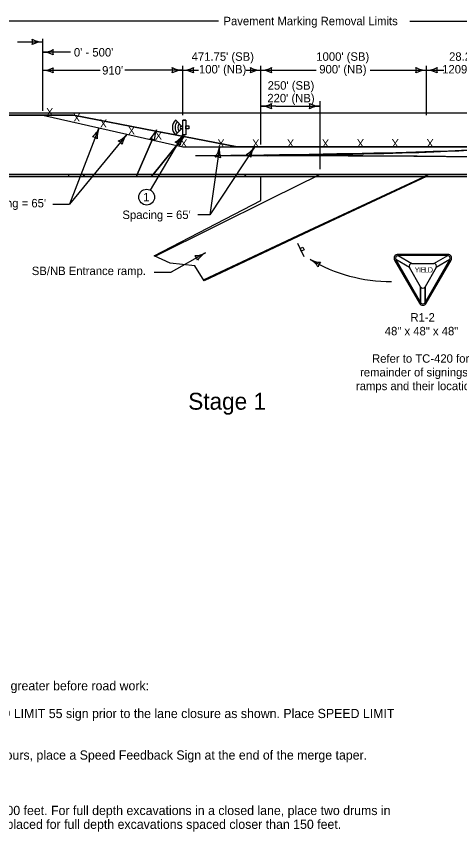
# Model space of a CAD drawing. Extents: x 10124 to 16850, y 7924 to 12166.
# Drawn here: x 11298 to 12139, y 8001 to 9547 of the extents above; entities that cross this region are included whole.
import ezdxf

# ---------------------------------------------------------------- set-up
doc = ezdxf.new("R2010")
doc.units = 0
for name, color, linetype in [('dsnShtPlotShapeBatchPrint', 7, 'Continuous'), ('dsnStdBlock', 7, 'Continuous'), ('dsnStdLabel', 7, 'Continuous'), ('dsnStdLineWork', 7, 'Continuous'), ('dsnStdShading', 7, 'Continuous'), ('Level 2', 7, 'Continuous'), ('SheetText', 7, 'Continuous')]:
    doc.layers.add(name, color=color, linetype=linetype)

msp = doc.modelspace()

# ---------------------------------------------------------------- linework, layer by layer
at = {"layer": 'dsnShtPlotShapeBatchPrint'}
msp.add_circle((11545.2, 9204), 15, dxfattribs=at)
at = {"layer": 'dsnStdLabel'}
for p, q in [((11619.5, 9349.7), (11619.5, 9322.2)), ((11831.5, 9116.4), (11843.2, 9091.5)), ((12116.2, 9095.5), (12022.1, 9095.5)), ((12015.6, 9084.3), (12062.7, 9002.8)), ((12075.6, 9002.8), (12122.7, 9084.3)), ((12064.8, 9034.1), (12064.8, 9004.1)), ((12073.5, 9004.1), (12073.5, 9034.1))]:
    msp.add_line(p, q, dxfattribs=at)
for points in [[(11613.9, 9322.2), (11613.9, 9349.7), (11619.5, 9349.7), (11619.5, 9322.2)], [(11619.5, 9333.3), (11619.5, 9338.9), (11625.2, 9338.9), (11625.2, 9333.3)], [(11838.6, 9101.5), (11836.2, 9106.6), (11841.3, 9109), (11843.7, 9103.9)], [(12116.2, 9093), (12022.1, 9093), (12048.1, 9078), (12090.2, 9078), (12116.2, 9093)], [(12017.8, 9085.5), (12064.8, 9004.1), (12064.8, 9034.1), (12043.8, 9070.5), (12017.8, 9085.5)], [(12073.5, 9004.1), (12120.5, 9085.5), (12094.5, 9070.5), (12073.5, 9034.1), (12073.5, 9004.1)]]:
    msp.add_lwpolyline(points, close=True, dxfattribs=at)
for centre, radius, start, end in [((12022.1, 9088), 7.5, 90.0002, 209.9999), ((12022.1, 9088), 5, 89.9999, 210.0002), ((12022.1, 9088), 5, 89.9999, 210.0002), ((12116.2, 9088), 7.5, 330.0002, 89.9999), ((12116.2, 9088), 5, 330.0002, 89.9999), ((12116.2, 9088), 5, 330.0002, 89.9999), ((12048.1, 9073), 5, 90.0002, 209.9999), ((12048.1, 9073), 5, 90.0002, 209.9999), ((12090.2, 9073), 5, 330.0002, 89.9999), ((12090.2, 9073), 5, 330.0002, 89.9999), ((12069.1, 9036.6), 5, 209.9999, 330.0002), ((12069.1, 9006.6), 7.5, 209.9999, 330.0002), ((12069.1, 9006.6), 5, 210.0002, 330.0016)]:
    msp.add_arc(centre, radius, start, end, dxfattribs=at)
at = {"layer": 'dsnStdLineWork'}
for p, q in [((10151.9, 9359), (11348.1, 9359)), ((11348.1, 9359), (11613.9, 9299.3)), ((11613.9, 9299.3), (12271.7, 9299.3)), ((10144, 9247), (11762.1, 9247)), ((11762.1, 9247), (11874.2, 9247)), ((12080.5, 9247), (12270.6, 9247))]:
    msp.add_line(p, q, dxfattribs=at)
for points in [[(11874.2, 9247), (11780.9, 9200.8), (11562, 9092.3)], [(11653.1, 9047.2), (11853.4, 9141.4), (12080.5, 9247)]]:
    msp.add_lwpolyline(points, dxfattribs=at)
at = {"layer": 'dsnStdShading'}
for p, q in [((12409.6, 9363), (11195.2, 9363)), ((11406.5, 9359), (11195.2, 9359)), ((11195.2, 9359), (11406.5, 9359)), ((11562.7, 9329), (11406.5, 9359)), ((11406.5, 9359), (11562.7, 9329)), ((11562.8, 9329), (11615.6, 9318.8)), ((11615.6, 9318.8), (11562.8, 9329)), ((11615.7, 9318.8), (11717.2, 9299.3)), ((11717.2, 9299.3), (11615.7, 9318.8)), ((11527.5, 9247), (11556.1, 9313.6)), ((11556.1, 9313.6), (11527.5, 9247)), ((11557.5, 9247), (11604.7, 9305.4)), ((11604.7, 9305.4), (11557.5, 9247)), ((11717.2, 9299.3), (12245.9, 9299.3)), ((12278.7, 9299.3), (11717.2, 9299.3)), ((11527.5, 9247), (10143.9, 9247)), ((10147.9, 9243), (11554.2, 9243)), ((10147.9, 9243), (11525.7, 9243)), ((10978.7, 9247), (11527.5, 9247)), ((11398.2, 9247), (11396.6, 9243)), ((11396.6, 9243), (11425.2, 9243)), ((11428.3, 9247), (11398.2, 9247)), ((11425.2, 9243), (11428.3, 9247)), ((11525.7, 9243), (11527.5, 9247)), ((11527.5, 9247), (11525.7, 9243)), ((11525.7, 9243), (11554.2, 9243)), ((11557.5, 9247), (11527.5, 9247)), ((11527.5, 9247), (11557.5, 9247)), ((11557.5, 9247), (11554.2, 9243)), ((11554.2, 9243), (11557.5, 9247)), ((11554.2, 9243), (12204, 9243)), ((12207, 9247), (11557.5, 9247)), ((11733.4, 9247), (11730.5, 9243)), ((11730.5, 9243), (12280.5, 9243)), ((12285.5, 9247), (11733.4, 9247)), ((11762.1, 9197.5), (11762.1, 9243)), ((11762.1, 9243), (12076.1, 9243)), ((12076.1, 9243), (11854.4, 9139.2)), ((11559.7, 9092.5), (11762.1, 9197.5)), ((11854.4, 9139.2), (11654.4, 9045.2)), ((11589.8, 9078.9), (11559.7, 9092.5)), ((11636.6, 9073.9), (11589.8, 9078.9)), ((11654.4, 9045.2), (11636.6, 9073.9))]:
    msp.add_line(p, q, dxfattribs=at)
for points in [[(11563.3, 9330.3), (11563.7, 9331.2), (11563.7, 9331.2)], [(11563.3, 9330.3), (11563.3, 9330.3)], [(11615.7, 9318.8), (11615.6, 9318.8)], [(11616.4, 9319.8), (11616.8, 9320.3), (11616.8, 9320.3)], [(11557.5, 9247), (12276.5, 9247), (12274.6, 9247)]]:
    msp.add_lwpolyline(points, dxfattribs=at)
for centre, radius, start, end in [((11524.5, 9347.6), 42.5, 309.2655, 336.072), ((11524.5, 9347.6), 42.5, 309.2655, 334.0959), ((11602.9, 9314.8), 42.5, 160.5422, 185.4105), ((11602.9, 9314.8), 42.5, 160.5422, 185.4105), ((11524.5, 9347.6), 42.5, 334.0959, 336.072), ((11602.9, 9314.8), 42.5, 157.3556, 160.5422), ((11602.9, 9314.8), 42.5, 158.6034, 160.5422), ((11524.5, 9347.6), 42.5, 337.3204, 337.338), ((11583.6, 9346.8), 42.5, 293.3393, 318.8219), ((11583.6, 9346.8), 42.5, 293.3393, 318.8219), ((11650.1, 9293.8), 42.5, 143.9415, 169.4842), ((11650.1, 9293.8), 42.5, 143.9415, 169.4842), ((11583.6, 9346.8), 42.5, 318.8219, 320.5615), ((11650.1, 9293.8), 42.5, 141.4294, 143.9415), ((11583.6, 9346.8), 42.5, 321.3942, 321.4118), ((11550, 9298.3), 16.4, 68.0792, 85.0713), ((11550, 9298.3), 16.4, 49.6046, 85.0713), ((11550, 9298.3), 16.4, 49.6046, 68.0792), ((11594.6, 9292.5), 16.4, 51.9095, 69.1451), ((11594.6, 9292.5), 16.4, 33.6784, 69.1451), ((11594.6, 9292.5), 16.4, 33.6784, 51.9095)]:
    msp.add_arc(centre, radius, start, end, dxfattribs=at)
for centre, major_axis, ratio, start_param, end_param in [((6674, 9331.8), (5526.2, -32.7), 0.008175, 5.82835, 6.279465), ((8643.8, 9315.3), (3556.3, -16.3), 0.011041, 5.788962, 6.278612), ((9224.4, 9266.8), (2972.6, 11.6), 0.003601, 0.004187, 0.623197), ((9959, 9266), (2238, 12.4), 0.004792, 0.005553, 0.624564)]:
    msp.add_ellipse(centre, major_axis=major_axis, ratio=ratio, start_param=start_param, end_param=end_param, dxfattribs=at)
at = {"layer": 'Level 2'}
for p, q in [((11599.8, 9350.1), (11613.9, 9336)), ((11619.5, 9349.7), (11613.9, 9349.7)), ((11613.9, 9336), (11599.8, 9321.8)), ((11619.5, 9322.2), (11613.9, 9322.2))]:
    msp.add_line(p, q, dxfattribs=at)
for radius, start, end in [(20.3, 135.88, 224.0313), (15.3, 136.1665, 223.7159), (10.3, 136.7294, 223.0963), (5.32, 138.7005, 221.2995)]:
    msp.add_arc((11614.4, 9335.9), radius, start, end, dxfattribs=at)
at = {"layer": 'SheetText'}
for p, q in [((11681.5, 9537.7), (11204.6, 9537.7)), ((12044.7, 9537.7), (12521.7, 9537.7)), ((11348.1, 9367.2), (11348.1, 9503.9)), ((11300.4, 9498.3), (11348.1, 9498.3)), ((11400.6, 9478.4), (11348.1, 9478.4)), ((11456.8, 9444.2), (11348.1, 9444.2)), ((11613.9, 9444.3), (11503.9, 9444.3)), ((11613.9, 9359.3), (11613.9, 9452.8)), ((11613.9, 9444.3), (11643.4, 9444.3)), ((11734.1, 9444.3), (11762.1, 9444.3)), ((11762.1, 9303.7), (11762.1, 9452.8)), ((11762.1, 9444.3), (11866.8, 9444.3)), ((11969.4, 9444.3), (12076.1, 9444.3)), ((12076.1, 9359.3), (12076.1, 9452.8)), ((12076.1, 9444.3), (12109.1, 9444.3)), ((11874.2, 9257.1), (11874.2, 9386)), ((11790.1, 9376.3), (11762.1, 9376.3)), ((11790.1, 9376.3), (11874.2, 9376.4)), ((11454.7, 9334.8), (11399.2, 9190.3)), ((11507.5, 9322.8), (11399.2, 9190.3)), ((11613.9, 9322.2), (11552.2, 9217.2)), ((11749.5, 9298.9), (11665.1, 9170.5)), ((11683.5, 9298.9), (11665.1, 9170.5)), ((11367.2, 9190.3), (11399.2, 9190.3)), ((11665.1, 9170.5), (11642, 9170.5)), ((11656.8, 9098.3), (11591.5, 9062)), ((11559.5, 9062), (11591.5, 9062))]:
    msp.add_line(p, q, dxfattribs=at)
for centre, radius, start, end in [((11312.5, 9498.2), 16.4, 342.2666, 17.7334), ((11348.1, 9540.7), 42.5, 241.9275, 270), ((11348.1, 9455.7), 42.5, 90, 118.0725), ((11348.1, 9520.9), 42.5, 270, 298.0725), ((11348.1, 9435.9), 42.5, 61.9275, 90), ((11383.8, 9478.4), 16.4, 162.2666, 197.7334), ((11348.1, 9486.7), 42.5, 270, 298.0725), ((11348.1, 9401.7), 42.5, 61.9275, 90), ((11383.8, 9444.2), 16.4, 162.2666, 197.7334), ((11578.3, 9444.3), 16.4, 342.2666, 17.7334), ((11613.9, 9486.8), 42.5, 241.9275, 270), ((11613.9, 9401.8), 42.5, 90, 118.0725), ((11613.9, 9486.8), 42.5, 270, 298.0725), ((11613.9, 9401.8), 42.5, 61.9275, 90), ((11649.6, 9444.3), 16.4, 162.2666, 197.7334), ((11726.5, 9444.3), 16.4, 342.2666, 17.7334), ((11762.1, 9486.8), 42.5, 241.9275, 270), ((11762.1, 9401.8), 42.5, 90, 118.0725), ((11762.1, 9486.8), 42.5, 270, 298.0725), ((11762.1, 9401.8), 42.5, 61.9275, 90), ((11797.7, 9444.3), 16.4, 162.2666, 197.7334), ((12040.4, 9444.3), 16.4, 342.2666, 17.7334), ((12076.1, 9486.8), 42.5, 241.9275, 270), ((12076.1, 9401.8), 42.5, 90, 118.0725), ((12076.1, 9486.8), 42.5, 270, 298.0725), ((12076.1, 9401.8), 42.5, 61.9275, 90), ((12111.7, 9444.3), 16.4, 162.2666, 197.7334), ((11762.1, 9418.8), 42.5, 270, 298.0725), ((11797.7, 9376.3), 16.4, 162.2666, 197.7334), ((11838.6, 9376.4), 16.4, 342.2666, 17.7333), ((11874.2, 9418.9), 42.5, 241.9275, 270), ((11762.1, 9333.8), 42.5, 61.9275, 90), ((11874.2, 9333.9), 42.5, 90, 118.0725), ((11415.5, 9351.2), 42.5, 309.2655, 337.338), ((11493.9, 9318.4), 42.5, 157.338, 185.4105), ((11441, 9301.9), 16.4, 49.6046, 85.0713), ((11474.3, 9349.3), 42.5, 293.3393, 321.4118), ((11540.7, 9296.3), 42.5, 141.4118, 169.4842), ((11577.7, 9344.5), 42.5, 300.2855, 328.358), ((11650.1, 9299.9), 42.5, 148.358, 176.4305), ((11485.3, 9295), 16.4, 33.6784, 69.1451), ((11595.2, 9291.9), 16.4, 40.6246, 76.0913), ((11641.6, 9305.8), 42.5, 322.5687, 350.6412), ((11725.5, 9292), 42.5, 170.6412, 198.7137), ((11714, 9322.2), 42.5, 298.6127, 326.6852), ((11785, 9275.6), 42.5, 146.6852, 174.7577), ((11677.7, 9263.7), 16.4, 62.9079, 98.3746), ((11729.9, 9269.1), 16.4, 38.9518, 74.4185), ((11636.1, 9135.5), 42.5, 271.0181, 299.0906), ((11625.6, 9081), 16.4, 11.3573, 46.824), ((11677.4, 9061.2), 42.5, 119.0906, 147.1631), ((12009.2, 9348.6), 304.7, 239.624, 270.1276), ((11875.4, 9123.1), 42.5, 241.5824, 269.6549), ((11834.9, 9048.4), 42.5, 33.5099, 61.5824), ((11886.5, 9068.8), 16.4, 133.849, 169.3157)]:
    msp.add_arc(centre, radius, start, end, dxfattribs=at)

# ---------------------------------------------------------------- texts
at = {"layer": 'dsnShtPlotShapeBatchPrint'}
msp.add_text('1', height=16, dxfattribs=at).set_placement((11538.8, 9196))
at = {"layer": 'dsnStdBlock'}
msp.add_text('Stage 1', height=32, dxfattribs=at).set_placement((11624.1, 8801.1))
at = {"layer": 'dsnStdLabel'}
for p in [(11368.1, 9373.1), (11419.4, 9362.3), (11470, 9351.2), (11523.4, 9337.9), (11574.6, 9328), (11622.4, 9313.7), (11693, 9313.7), (11759, 9313.7), (11824.9, 9313.7), (11891.2, 9313.7), (11957.5, 9313.8), (12023.4, 9313.8), (12089.6, 9313.9)]:
    msp.add_text('X', height=15, rotation=180, dxfattribs=at).set_placement(p)
for s, p in [('Y', (12053.5, 9061.1)), ('I', (12061.5, 9061.1)), ('E', (12065, 9061.1)), ('L', (12071.7, 9061.1)), ('D', (12078.4, 9061.1))]:
    msp.add_text(s, height=10, dxfattribs=at).set_placement(p)
at = {"layer": 'SheetText'}
for s, height, p in [('Pavement Marking Removal Limits', 16, (11690.9, 9529.7)), ("0' - 500'", 16, (11407.3, 9470.4)), ("471.75' (SB)", 16, (11630.5, 9462.3)), ("1000' (SB)", 16, (11867, 9462.3)), ("28.25' (SB)", 16, (12118.8, 9462.3)), ("910'", 16, (11460.8, 9436.2)), ("100' (NB)", 16, (11644.5, 9438.3)), ("900' (NB)", 16, (11872.6, 9438.3)), ("1209.25' (NB)", 16, (12105.7, 9438.3)), ("250' (SB)", 16, (11774.7, 9407.6)), ("220' (NB)", 16, (11774.1, 9383.6)), ("Spacing = 65'", 16, (11224.9, 9184.5)), ("Spacing = 65'", 16, (11499.3, 9162.5)), ('SB/NB Entrance ramp.', 16, (11327.4, 9056.2)), ('R1-2', 16, (12045.5, 8968.1)), ('48" x 48" x 48"', 16, (11996.9, 8942.1)), ('Refer to TC-420 for', 16, (11972.7, 8890.1)), ('remainder of signings at', 16, (11950, 8864.1)), ('ramps and their locations.', 16, (11942.2, 8838.1)), ('For roadways with a posted speed limit of 60 mph or greater before road work:', 17.5, (10738.2, 8269.2)), ('Place SPEED LIMIT AHEAD sign and SPEED LIMIT 55 sign prior to the lane closure as shown. Place SPEED LIMIT', 17.5, (10808.2, 8216.7)), ('For traffic control zones lasting more than 4 hours, place a Speed Feedback Sign at the end of the merge taper.', 17.5, (10808.2, 8137.9)), ('For lanes closed to traffic, place two drums every 1000 feet. For full depth excavations in a closed lane, place two drums in ', 17.5, (10738.2, 8032.9)), ('front of each location. Additional drums need not be placed for full depth excavations spaced closer than 150 feet.', 17.5, (10738.2, 8006.7))]:
    msp.add_text(s, height=height, dxfattribs=at).set_placement(p)

doc.saveas('drawing.dxf')
